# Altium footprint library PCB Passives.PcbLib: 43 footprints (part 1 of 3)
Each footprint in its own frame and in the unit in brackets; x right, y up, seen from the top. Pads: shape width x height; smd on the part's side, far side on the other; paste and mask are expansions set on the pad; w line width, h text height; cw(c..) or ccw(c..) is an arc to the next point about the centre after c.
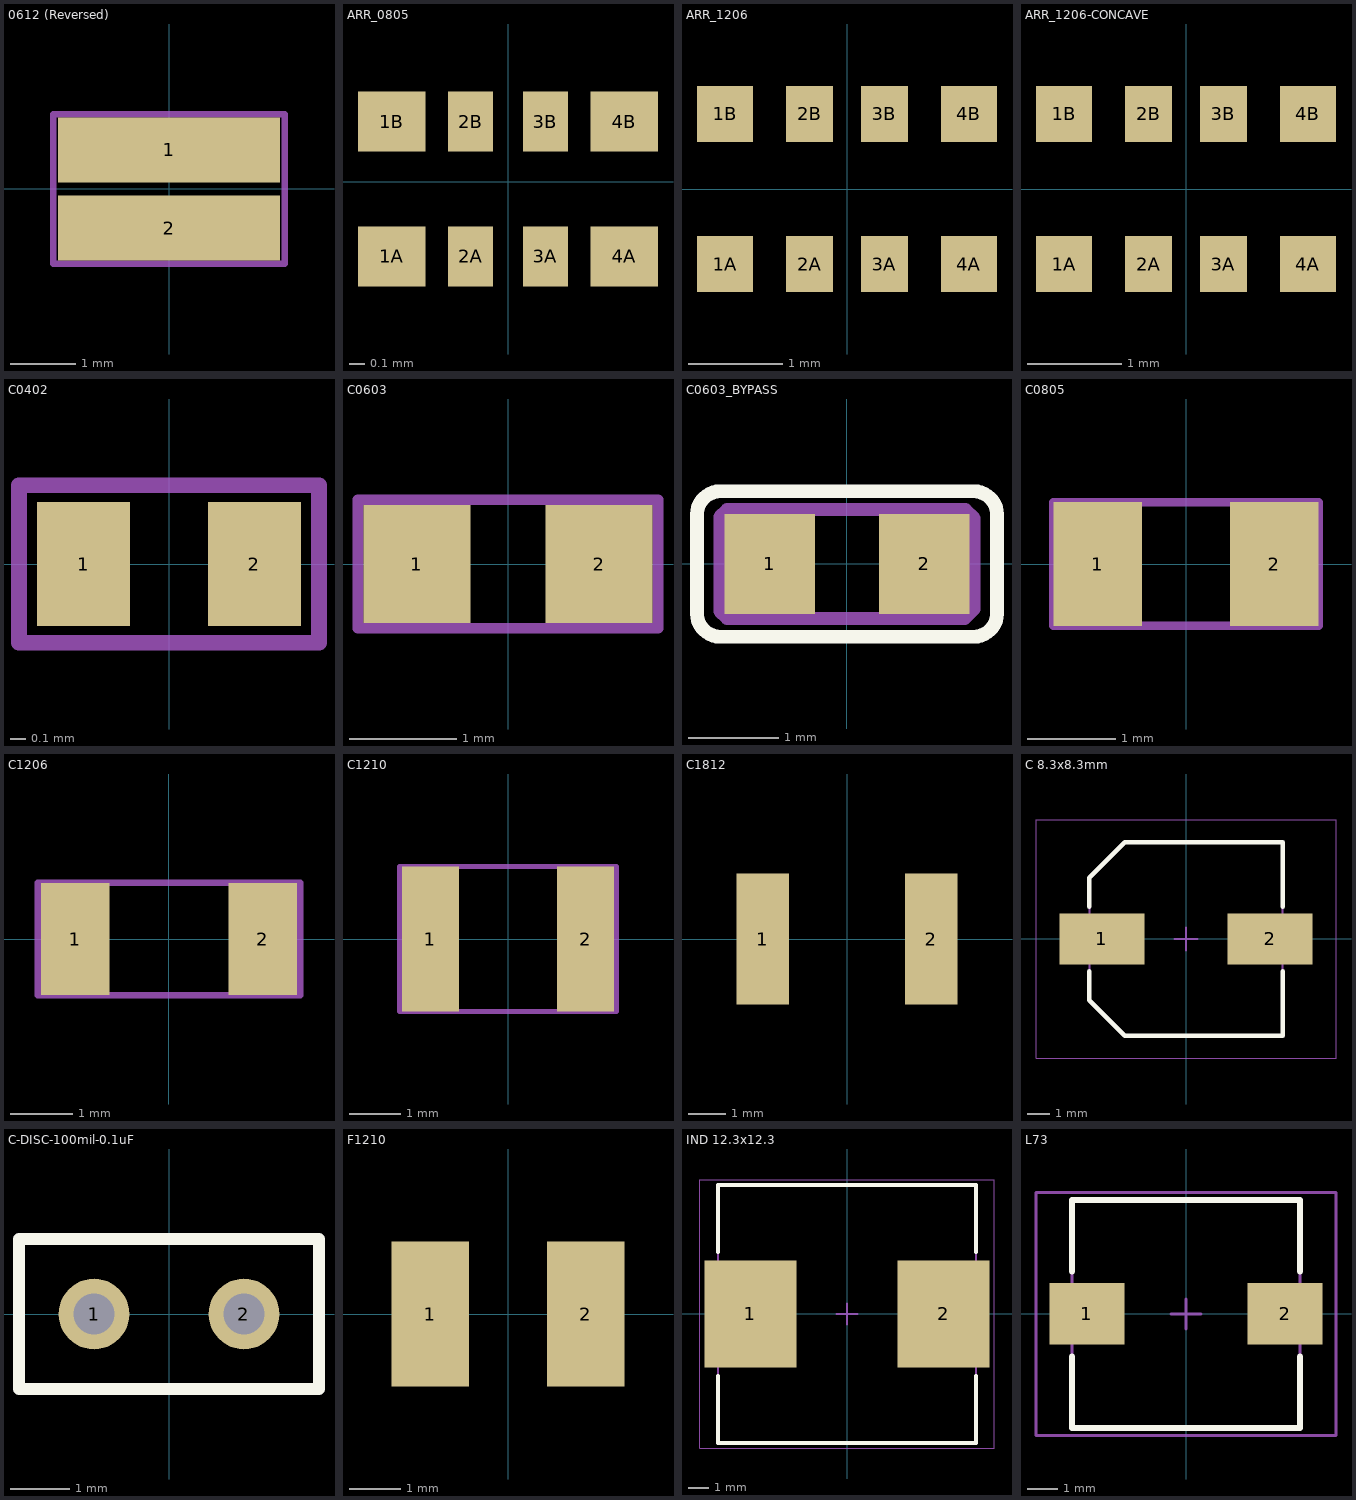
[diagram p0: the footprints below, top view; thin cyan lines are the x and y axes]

## 0612 (Reversed) [mm] "Chip Resistor, 2-Leads, Body 1,60x3,20mm, IPC Medium Density"
height 0.6
pads (2):
  rect 3.4x1 smd: 1(0,0.6) 2(0,-0.6)
Mechanical 29:
  lines w0.1: -1.778,-1.143 -1.778,1.143 1.778,1.143 1.778,-1.143 -1.778,-1.143
  text ".Designator" at -1.165,-0.3 h0.7
3D body "RESC1632X06N.step": height 0.6, standoff 0, extent -1.7,-0.9 1.7,0.9

## ARR_0805 [mm]
pads (8):
  rect 0.45x0.4 smd: 1A(-0.775,-0.5) 1B(-0.775,0.4) 4A(0.775,-0.5) 4B(0.775,0.4)
  rect 0.3x0.4 smd: 2A(-0.25,-0.5) 2B(-0.25,0.4) 3A(0.25,-0.5) 3B(0.25,0.4)
3D body "User Library-YC124.step": height 0.36, standoff 0, extent -1,-0.55 1,0.45

## ARR_1206 [mm]
height 0.6
pads (8):
  rect 0.6x0.6 smd: 1A(-1.3,-0.8) 1B(-1.3,0.8) 4A(1.3,-0.8) 4B(1.3,0.8)
  rect 0.5x0.6 smd: 2A(-0.4,-0.8) 2B(-0.4,0.8) 3A(0.4,-0.8) 3B(0.4,0.8)
3D body "User Library-YC164.step": height 0.55, standoff 0, extent -1.6,-0.8 1.6,0.8

## ARR_1206-CONCAVE [mm]
height 0.6
pads (8):
  rect 0.6x0.6 smd: 1A(-1.3,-0.8) 1B(-1.3,0.8) 4A(1.3,-0.8) 4B(1.3,0.8)
  rect 0.5x0.6 smd: 2A(-0.4,-0.8) 2B(-0.4,0.8) 3A(0.4,-0.8) 3B(0.4,0.8)
3D body "CAT16-x4.stp": height 0.6, standoff 0, extent -1.775,-0.825 1.575,0.925

## C0402 [mm] "0402 ceramic capacitor"
pads (2):
  rect 0.6x0.8 smd: 1(-0.55,0) 2(0.55,0)
Mechanical 29:
  lines w0.1: -0.965,-0.508 -0.965,0.508 0.965,0.508 0.965,-0.508 -0.965,-0.508
  text ".Designator" at -0.787,-0.279 h0.6
3D body "CAP_0402.step": height 0.5, standoff 0, extent -0.5,-0.25 0.5,0.25

## C0603 [mm] "0603 ceramic capacitor"
pads (2):
  rect 1x1.1 smd: 1(-0.85,0) 2(0.85,0)
Mechanical 29:
  lines w0.1: -1.4,-0.6 1.4,-0.6 1.4,0.6 -1.4,0.6 -1.4,-0.6
  text ".Designator" at -1.2,-0.2 h0.6
3D body "CAP_0603.step": height 0.8, standoff 0, extent -0.8,-0.4 0.8,0.4

## C0603_BYPASS [mm] "0603 ceramic capacitor"
pads (2):
  rect 1x1.1 smd: 1(-0.85,0) 2(0.85,0)
Top Overlay:
  lines w0.152: -1.651,-0.546 ccw(c-1.397,-0.546) -1.397,-0.8 1.397,-0.8 ccw(c1.397,-0.546) 1.651,-0.546 1.651,0.546 ccw(c1.397,0.546) 1.397,0.8 -1.397,0.8 ccw(c-1.397,0.546) -1.651,0.546 -1.651,-0.546
Mechanical 29:
  lines w0.14: -1.4,-0.521 -1.4,0.521 -1.321,0.6 1.305,0.6 1.4,0.505 1.4,-0.495 1.295,-0.6 -1.321,-0.6 -1.4,-0.521
  text ".Designator" at -0.635,-0.254 h0.51
3D body "CAP_0603.step": height 0.8, standoff 0, extent -0.8,-0.4 0.8,0.4

## C0805 [mm] "0805 ceramic capacitor"
pads (2):
  rect 1x1.4 smd: 1(-1,0) 2(1,0)
Mechanical 29:
  lines w0.1: -1.5,-0.7 1.5,-0.7 1.5,0.7 -1.5,0.7 -1.5,-0.7
  text ".Designator" at -1.3,-0.2 h0.6
3D body "CAP_0805.step": height 0.6, standoff 0, extent -1,-0.625 1,0.625

## C1206 [mm] "1206 ceramic capacitor"
pads (2):
  rect 1.1x1.8 smd: 1(-1.5,0) 2(1.5,0)
Mechanical 29:
  lines w0.1: -2.1,-0.9 -2.1,0.9 2.1,0.9 2.1,-0.9 -2.1,-0.9
  text ".Designator" at -1.8,-0.233 h0.7
3D body "CAP_1206.step": height 0.76, standoff -0.01, extent -1.6,-0.8 1.6,0.8

## C1210 [mm] "1210 capacitor"
pads (2):
  rect 1.1x2.8 smd: 1(-1.5,0) 2(1.5,0)
Mechanical 29:
  lines w0.1: -2.1,-1.4 2.1,-1.4 2.1,1.4 -2.1,1.4 -2.1,-1.4
  text ".Designator" at -1.8,-0.4 h0.8
3D body "User Library-SMD CAPACITOR.step": height 0.77, standoff -0.01, extent -1.6,-1.25 1.6,1.25

## C1812 [mm] "1812 capacitor"
pads (2):
  rect 1.4x3.5 smd: 1(-2.25,0) 2(2.25,0)
3D body "User Library-SMD CAPACITOR(1).step": height 1, standoff 0, extent -2.25,-1.6 2.25,1.6

## C 8.3x8.3mm [mm] "Aluminum Electrolytic Capacitor, Body 8.30x8.30x11.70mm, IPC Low Density"
height 11.7
pads (2):
  rect 3.75x2.25 smd: 1(-3.7,0) 2(3.7,0)
Top Overlay:
  lines w0.2: -4.25,-1.425 -4.25,-2.688 -2.688,-4.25 4.25,-4.25 4.25,-1.425 ; -4.25,1.425 -4.25,2.687 -2.688,4.25 4.25,4.25 4.25,1.425
Mechanical 13:
  lines w0.1: -4.25,-2.688 -4.25,2.687 -2.688,4.25 4.25,4.25 4.25,-4.25 -2.688,-4.25 -4.25,-2.688
Mechanical 15:
  lines w0.05: -6.6,-5.25 6.6,-5.25 6.6,5.25 -6.6,5.25 -6.6,-5.25
  lines w0.1: -0.5,0 0.5,0 ; 0,-0.5 0,0.5
3D body: height 11.7, standoff 0, extent -4.25,-4.25 4.25,4.247
3D body: height 3.9, standoff 0, extent -4.25,-4.25 4.25,4.25

## C-DISC-100mil-0.1uF [mm]
pads (2):
  round 1.2 hole 0.7: 1(-1.27,0) 2(1.27,0)
Top Overlay:
  lines w0.2: -2.54,-1.27 -2.54,1.27 2.54,1.27 2.54,-1.27 -2.54,-1.27
3D body "10pF Ceramic Disc 2.STEP": height 6.16, standoff -7.87, extent -2.35,-1.25 2.35,1.25

## F1210 [mm]
pads (2):
  rect 1.5x2.8 smd: 1(-1.5,0) 2(1.5,0)
3D body "User Library-Fuse1210.step": height 0.67, standoff 0, extent -1.607,-1.287 1.608,1.288

## IND 12.3x12.3 [mm] "Precision Wire Wound Inductor, 2-Leads, Body 12.30x12.30mm, IPC Medium Density"
height 6
pads (2):
  rect 4.4x5.1 smd: 1(-4.6,0) 2(4.6,0)
Top Overlay:
  lines w0.2: -6.15,-2.95 -6.15,-6.15 6.15,-6.15 6.15,-2.95 ; -6.15,2.95 -6.15,6.15 6.15,6.15 6.15,2.95
Mechanical 13:
  lines w0.1: -6.15,-6.15 6.15,-6.15 6.15,6.15 -6.15,6.15 -6.15,-6.15
Mechanical 15:
  lines w0.05: -7.025,-6.4 7.025,-6.4 7.025,6.4 -7.025,6.4 -7.025,-6.4
  lines w0.1: -0.5,0 0.5,0 ; 0,-0.5 0,0.5
3D body: height 6, standoff 0, extent -6.15,-6.15 6.15,6.15

## L73 [mm] "Inductor 7.3x7.3mm"
height 3.55
pads (2):
  rect 2.5x2.05 smd: 1(-3.3,0) 2(3.3,0)
Top Overlay:
  lines w0.2: -3.8,-1.425 -3.8,-3.8 3.8,-3.8 3.8,-1.425 ; -3.8,1.425 -3.8,3.8 3.8,3.8 3.8,1.425
Mechanical 13:
  lines w0.1: -3.8,-3.8 3.8,-3.8 3.8,3.8 -3.8,3.8 -3.8,-3.8
Mechanical 15:
  lines w0.1: -0.5,0 0.5,0 ; 0,-0.5 0,0.5 ; -5,-4.05 5,-4.05 5,4.05 -5,4.05 -5,-4.05
3D body "User Library-Murata_4600.step": height 4.55, standoff 0, extent -3.764,-3.65 3.664,3.65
